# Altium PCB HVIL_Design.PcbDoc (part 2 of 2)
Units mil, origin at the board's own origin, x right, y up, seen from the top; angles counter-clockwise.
Board outline 4950 x 3450 mil, 2 copper layers (Top Layer, Bottom Layer), stack 62 mil thick; 93 components, 48 nets, 203 pads, 53 vias.
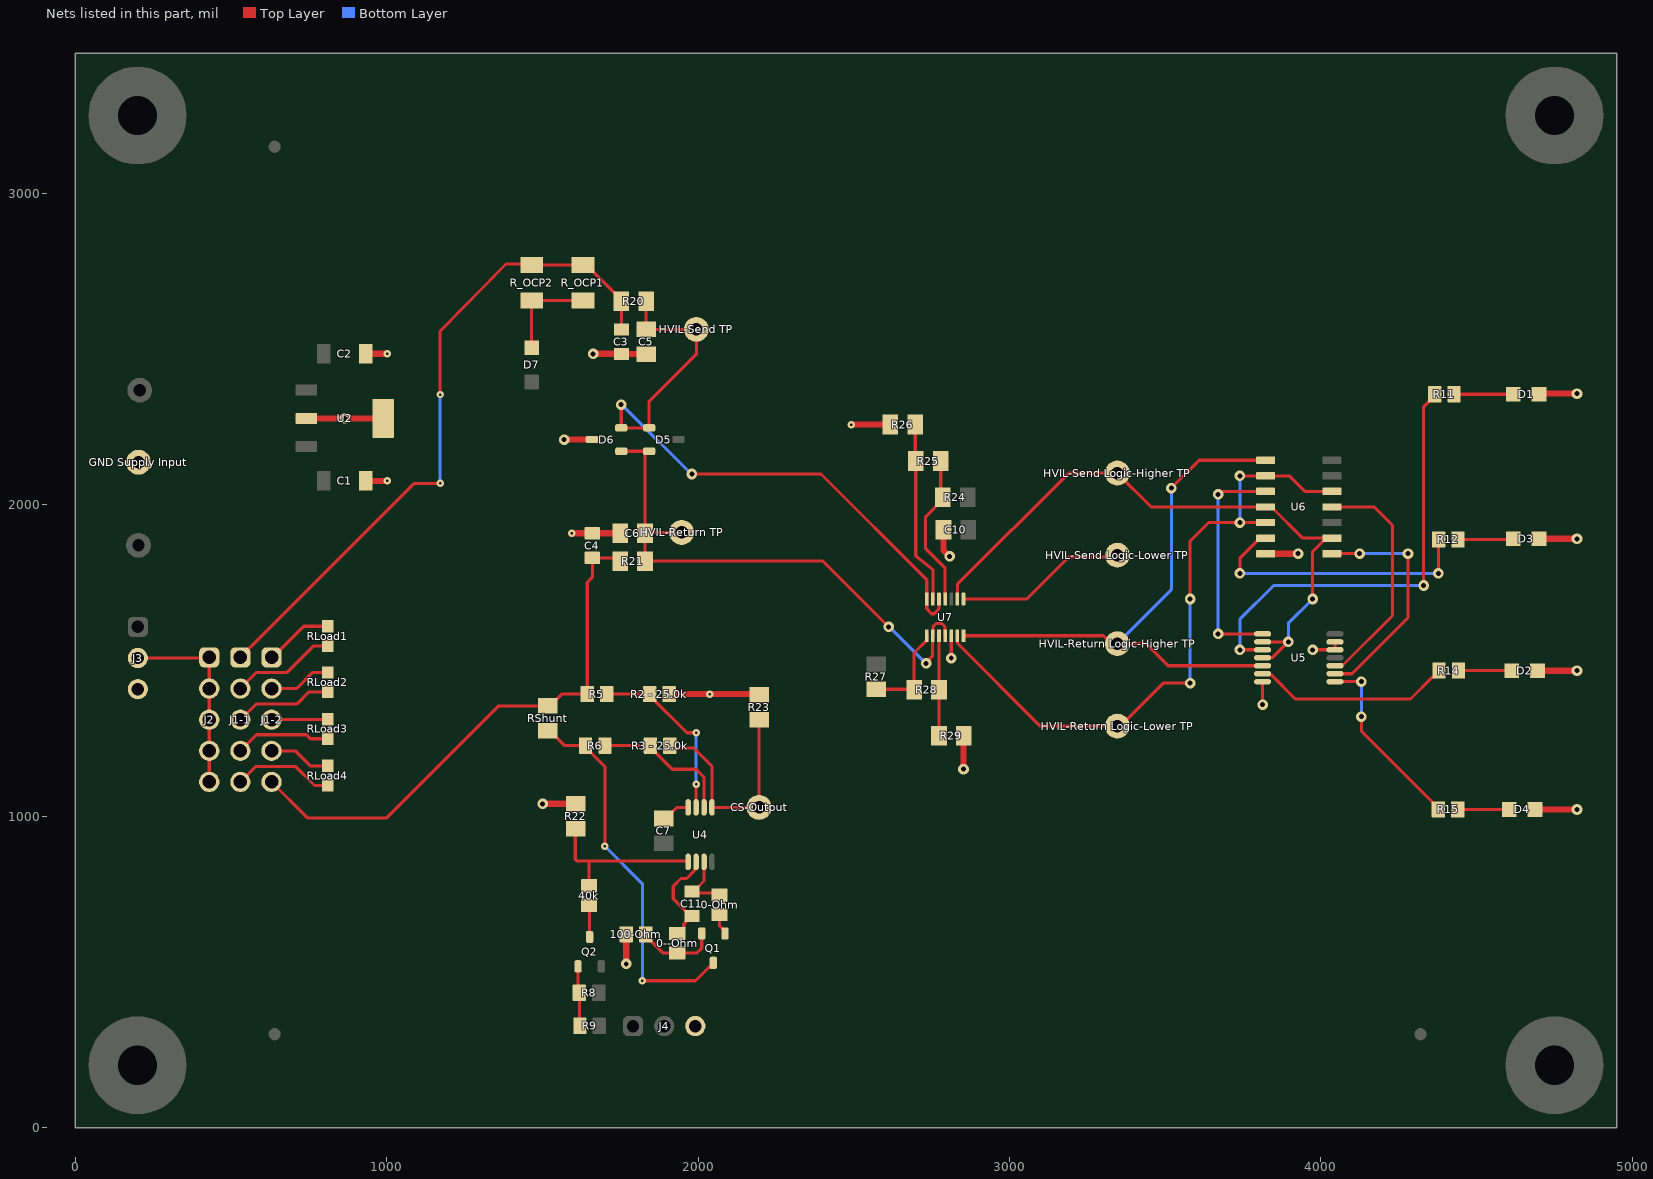
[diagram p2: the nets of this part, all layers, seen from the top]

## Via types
v1: diameter 34, hole 16, Top Layer to Bottom Layer, tented both sides, 42 vias
v2: diameter 24, hole 8, Top Layer to Bottom Layer, tented both sides, 11 vias

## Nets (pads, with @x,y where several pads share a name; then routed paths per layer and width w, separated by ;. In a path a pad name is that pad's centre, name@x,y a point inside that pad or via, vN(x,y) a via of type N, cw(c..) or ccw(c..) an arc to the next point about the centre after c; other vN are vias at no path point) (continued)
GND: 100-Ohm.2 "GND Supply Input.1" "R2 - 25.0k.2" C1.1 C2.1 C3.2 C4.2 C5.1 C6.1 C7.2 C10.2 D1.2 D2.2 D3.2 D4.2 D6.3 J3.3 J4.3 R22.2 R23.2 R26.2 R29.2 U2.2 U2.4 U4.4 U5.7 U5.12 U5.13 U6.7 U7.12 | length 2583.6
  Top Layer w10: C1.1@932.09,2076.77 C1.1@932.09,2086.61 ; C2.1@932.09,2475.21 C2.1@932.09,2485.06 ; v2(1594.88,1908.39) v2@1594.96,1908.46 ; C6.1@1749.3,1908.46 C6.1@1749.37,1908.39 ; C3.2@1753.13,2485.06 C3.2@1753.94,2484.25 ; 100-Ohm.2@1766.35,617.62 100-Ohm.2@1769.27,620.53 ; C5.1@1832.68,2484.25 C5.1@1833.31,2483.62 ; C7.2@1890,992.72 1896.5,992.72 1932.14,1028.36 U4.4@1967.84,1028.36 ; R23.2@2193.39,1392.13 R23.2@2195.87,1389.65 ; v1(2812.99,1507.78) U7.12@2812.99,1579.57 ; R29.2@2852.36,1257.65 R29.2@2853.62,1258.91 ; v1(3812.99,1358.41) U5.7@3812.99,1432.09 ; v1(3973.58,1534.45) U5.12@4045.28,1534.45 U5.13@4045.28,1560.04 ; D1.2@4700.79,2355.31 D1.2@4702.76,2357.28
  Top Layer w20: U2.2@742.13,2277.56 v1(865.16,2277.56) U2.4@988.19,2277.56 ; C1.1@932.09,2076.77 v2(1001.97,2076.77) ; C2.1@932.09,2485.06 v2(1001.97,2485.06) ; v1(1500.72,1039.72) R22.2@1607.29,1039.72 ; v1(1570.03,2209.66) D6.3@1658.82,2209.66 ; v2@1594.96,1908.46 C4.2@1660.43,1908.46 ; v1(1663.03,2485.06) C3.2@1753.13,2485.06 ; C4.2@1664.57,1908.46 C6.1@1749.3,1908.46 ; C3.2@1753.94,2484.25 C5.1@1832.68,2484.25 ; v1(1769.27,525.65) 100-Ohm.2@1769.27,620.53 ; 1907.23,1392.13 v2(2037.69,1392.13) R23.2@2193.39,1392.13 ; v2(2492.36,2257.87) R26.2@2617.48,2257.87 ; C10.2@2788.03,1920 2788.03,1853.84 v1(2807.62,1834.25) ; v1(2852.36,1150.99) R29.2@2852.36,1257.65 ; U6.7@3822.83,1843.11 v1(3927.17,1843.11) ; D4.2@4687.72,1021.65 v1(4822.56,1021.65) ; D2.2@4696.07,1467.52 v1(4822.56,1467.52) ; D3.2@4700.79,1891.05 v1(4822.56,1891.05) ; D1.2@4702.76,2357.28 v1(4822.56,2357.28)
"HVIL-Return Logic-Higher": "HVIL-Return Logic-Higher TP.1" U5.5 U6.1 U7.14 | length 1912
  Top Layer w10: U7.14@2852.36,1579.57 3302.08,1579.57 3327.51,1554.13 3346.46,1554.13 3439.14,1554.13 3510,1483.27 U5.5@3812.99,1483.27 ; v1(3520,2053.94) 3609.17,2143.11 U6.1@3822.83,2143.11
  Bottom Layer w10: 3346.46,1554.13 3520,1727.68 v1(3520,2053.94)
"HVIL-Return Logic-Lower": "HVIL-Return Logic-Lower TP.1" U6.2 U6.5 U6.12 U7.13 | length 2128.4
  Top Layer w10: U7.13@2832.68,1579.57 2833.58,1578.66 2833.58,1554.71 3098.92,1289.37 3346.46,1289.37 3355.61,1289.37 3493.51,1427.27 v1(3580,1427.27) ; v1(3580,1697.68) 3580,1883.11 3640,1943.11 v1(3740,1943.11) U6.5@3822.83,1943.11 ; v1(3740,2093.11) U6.2@3822.83,2093.11 3898.82,2093.11 3948.82,2043.11 U6.12@4035.43,2043.11
  Bottom Layer w10: v1(3580,1427.27) v1(3580,1697.68) ; v1(3740,1943.11) v1(3740,2093.11)
"HVIL-Send Logic-Higher": "HVIL-Send Logic-Higher TP.1" U5.2 U5.4 U6.4 U6.9 U7.2 | length 2053.8
  Top Layer w10: U7.2@2832.68,1697.68 2832.68,1744.65 3190,2101.97 3346.46,2101.97 3455.32,1993.11 U6.4@3822.83,1993.11 3841.54,1993.11 3941.54,1893.11 U6.9@4016.73,1893.11 ; U5.4@3812.99,1508.86 3814.47,1510.34 3845.82,1510.34 v1(3895.53,1560.04) U5.2@3812.99,1560.04 ; v1(3973.58,1697.68) 3973.58,1849.96 U6.9@4016.73,1893.11 ; U6.9@4035.43,1893.11 U6.9@4016.73,1893.11
  Bottom Layer w10: v1(3895.53,1560.04) 3895.53,1619.63 v1(3973.58,1697.68)
"HVIL-Send Logic-Lower": "HVIL-Send Logic-Lower TP.1" U7.1 | length 552.4
  Top Layer w10: U7.1@2852.36,1697.68 3055.4,1697.68 3190,1832.28 3340.34,1832.28 3346.46,1838.4
Net0--Ohm_1: 0--Ohm.1 100-Ohm.1 Q1.2 | length 261
  Top Layer w10: 100-Ohm.1@1831.77,620.53 1831.77,615.78 1886.54,561.01 0--Ohm.1@1932.95,561.01 1996.5,561.01 2011.77,576.28 Q1.2@2011.77,623.51
Net0--Ohm_2: 0--Ohm.2 C11.2 U4.6 | length 318.5
  Top Layer w10: 0--Ohm.2@1932.95,623.51 1937.7,623.51 1953.95,639.76 1953.95,653.18 1960.67,659.91 1960.67,664.83 C11.2@1975.36,679.51 ; C11.2@1980.28,679.51 C11.2@1975.36,679.51 ; U4.6@1993.43,853.16 1993.43,833.36 1989.57,829.5 1989.57,826.44 1963.13,800 1945.2,800 1920.32,775.12 1920.32,734.55 C11.2@1975.36,679.51
Net0-Ohm_1: 0-Ohm.1 Q1.1 | length 68.3
  Top Layer w10: 0-Ohm.1@2068.86,684 2068.86,647.75 2078.98,637.64 2079.84,637.64 2086.58,630.9 Q1.1@2086.58,623.51
Net0-Ohm_2: 0-Ohm.2 C11.1 U4.7 | length 207.3
  Top Layer w10: U4.7@2019.02,853.16 2019.02,792.08 1985.2,758.25 C11.1@1980.28,758.25 1985.34,753.19 2062.18,753.19 0-Ohm.2@2068.86,746.5
Net40k_1: 40k.1 Q2.3 | length 102.4
  Top Layer w10: 40k.1@1649.83,714 1651.57,712.27 Q2.3@1651.57,612.33
Net40k_2: 40k.2 R22.1 U4.5 | length 544.7
  Top Layer w10: R22.1@1607.29,959.72 1605.56,957.98 1605.56,861.74 1610.66,856.64 1649.83,856.64 ; 40k.2@1649.83,776.5 1649.83,856.64 ; U4.5@1967.84,853.16 1964.36,856.64 1649.83,856.64
NetC5_2: "HVIL-Send TP.1" C5.2 D5.1 D6.2 R20.2 U7.5 U7.7 | length 2186.3
  Top Layer w10: v1(1753.13,2321.62) 1753.22,2321.53 1753.22,2247.15 D6.2@1753.31,2247.06 D5.1@1842.91,2247.06 1842.91,2332.42 1994.43,2483.94 1994.43,2563.62 C5.2@1833.31,2563.62 R20.2@1833.31,2653.54 ; v1(1980,2099.18) 2394.55,2099.18 2734.25,1759.48 U7.7@2734.25,1697.68 2734.25,1665.75 2749.72,1650.28 2758,1650.28 2773.62,1665.91 U7.5@2773.62,1697.68
  Bottom Layer w10: v1(1753.13,2321.62) 1755.35,2321.62 1977.79,2099.18 v1(1980,2099.18)
NetC6_2: "HVIL-Return TP.1" C6.2 D5.2 D6.1 R21.2 U7.9 U7.11 | length 1819.5
  Top Layer w10: D6.1@1753.31,2172.26 D5.2@1836.11,2172.26 ; D5.2@1842.91,2172.26 D5.2@1836.11,2172.26 ; 1947.12,1911.42 1832.4,1911.42 C6.2@1829.37,1908.39 ; v1@2611.65,1601.77 v1(2611.65,1608.27) 2400.49,1819.43 R21.2@1829.37,1819.43 C6.2@1829.37,1908.39 ; v1(2732.5,1491.09) 2732.5,1494.7 2753.32,1515.52 2753.32,1578.95 U7.9@2753.94,1579.57 2753.94,1608.27 2764.76,1619.09 2782.13,1619.09 2793.31,1607.91 U7.11@2793.31,1572.83 ; C6.2@1829.37,1908.39 1829.37,2165.52 D5.2@1836.11,2172.26
  Bottom Layer w10: v1(2611.65,1608.27) 2613.49,1608.27 2730.67,1491.09 v1(2732.5,1491.09)
NetCS-Output_1: "R3 - 25.0k.2" CS-Output.1 R23.1 U4.1 | length 727.7
  Top Layer w10: 1909.2,1226.55 1916.84,1218.91 1986.54,1218.91 2044.61,1160.84 U4.1@2044.61,1028.36 CS-Output.1@2195.87,1028.36 R23.1@2195.87,1309.65
NetD1_1: D1.1 R11.2 | length 190.1
  Top Layer w10: R11.2@4428.04,2355.31 D1.1@4618.11,2355.31
NetD2_1: D2.1 R14.2 | length 171.7
  Top Layer w10: R14.2@4441.68,1467.52 D2.1@4613.39,1467.52
NetD3_1: D3.1 R12.2 | length 178.1
  Top Layer w10: R12.2@4440.81,1889.09 4616.14,1889.09 D3.1@4618.11,1891.05
NetD4_1: D4.1 R15.2 | length 165.3
  Top Layer w10: R15.2@4439.79,1021.65 D4.1@4605.05,1021.65
NetD7_1: D7.1 R_OCP1.1 R_OCP2.1 | length 316.5
  Top Layer w10: D7.1@1465.55,2504.74 R_OCP2.1@1465.55,2656.5 R_OCP1.1@1630.31,2656.5
NetQ1_3: Q1.3 R6.1 RShunt.2 | length 1227.4
  Top Layer w10: RShunt.2@1517.72,1274.37 1524.22,1274.37 1572.04,1226.55 R6.1@1638.45,1226.55 1638.45,1221.8 1700.95,1159.3 v2(1700.95,903.36) ; v2(1821.1,471.59) 1991.74,471.59 2035.05,514.9 2042.43,514.9 2049.18,521.64 Q1.3@2049.18,529.02
  Bottom Layer w10: v2(1700.95,903.36) 1821.1,783.21 v2(1821.1,471.59)
NetQ2_1: Q2.1 R8.2 R9.2 | length 193.3
  Top Layer w10: Q2.1@1614.17,517.84 1614.17,437.61 R8.2@1618.58,433.2 1619.45,432.33 1619.45,328 R9.2@1620.32,327.13
"NetR2 - 25.0k_1": "R2 - 25.0k.1" R5.2 U4.3 | length 580.8
  Top Layer w10: R5.2@1706.45,1392.13 1844.73,1392.13 1844.73,1387.38 1964.22,1267.89 v2(1993.43,1267.89) ; U4.3@1993.43,1028.36 v2(1993.43,1103.22)
  Bottom Layer w10: v2(1993.43,1103.22) v2(1993.43,1267.89)
"NetR3 - 25.0k_1": "R3 - 25.0k.1" R6.2 U4.2 | length 459.8
  Top Layer w10: R6.2@1700.95,1226.55 1846.7,1226.55 1846.7,1221.8 1917.52,1150.99 1993.43,1150.99 2019.02,1125.39 U4.2@2019.02,1028.36
NetR11_1: R11.1 U5.3 | length 1435.7
  Top Layer w10: v1(3740,1534.45) U5.3@3812.99,1534.45 ; v1(4330,1740.99) 4330,2315.03 4365.54,2350.56 R11.1@4365.54,2355.31
  Bottom Layer w10: v1(3740,1534.45) 3740,1632.17 3848.82,1740.99 4299.36,1740.99 ; 4300,1740.34 4299.36,1740.99 ; v1(4330,1740.99) 4299.36,1740.99
NetR12_1: R12.1 U6.6 | length 905.2
  Top Layer w10: v1(3740,1780) 3740,1828.98 3804.13,1893.11 U6.6@3822.83,1893.11 ; v1(4377.29,1780) 4377.29,1888.06 R12.1@4378.31,1889.09
  Bottom Layer w10: v1(3740,1780) v1(4377.29,1780)
NetR14_1: R14.1 U5.6 | length 640.5
  Top Layer w10: U5.6@3812.99,1457.68 3833.78,1457.68 3837.64,1453.82 3840.69,1453.82 3918.31,1376.21 4287.87,1376.21 4358.18,1446.52 4362.93,1446.52 4379.18,1462.77 R14.1@4379.18,1467.52
NetR15_1: R15.1 U5.8 | length 597.6
  Top Layer w10: U5.8@4045.28,1432.09 v1(4130,1432.09) ; v1(4130,1320) 4130,1273.69 4377.29,1026.4 R15.1@4377.29,1021.65
  Bottom Layer w10: v1(4130,1320) v1(4130,1432.09)
NetR24_2: R24.2 R25.1 U7.4 | length 495
  Top Layer w10: R25.1@2779.17,2140.76 2779.17,2031.35 R24.2@2786.32,2024.2 2786.32,2017.7 2730.67,1962.04 2730.67,1859.43 2793.31,1796.79 U7.4@2793.31,1697.68
NetR25_2: R25.2 R26.1 U7.6 | length 593.7
  Top Layer w10: R26.1@2697.48,2257.87 2697.48,2142.46 R25.2@2699.17,2140.76 2699.17,1835.53 2702.13,1832.58 2753.94,1790.89 U7.6@2753.94,1690.94
NetR27_2: R27.2 R28.1 U7.8 | length 312.9
  Top Layer w10: R27.2@2571.65,1407.78 2691.99,1407.78 R28.1@2693.62,1406.14 2693.62,1524.18 2734.25,1564.81 U7.8@2734.25,1579.57
NetR28_2: R28.2 R29.1 U7.10 | length 320.7
  Top Layer w10: R29.1@2773.62,1258.91 R28.2@2773.62,1406.14 U7.10@2773.62,1579.57
NetU5_1: U5.1 U6.3 | length 747.7
  Top Layer w10: v1(3670,1585.63) U5.1@3812.99,1585.63 ; v1(3670,2033.5) 3676.49,2033.5 3686.11,2043.11 U6.3@3822.83,2043.11
  Bottom Layer w10: v1(3670,1585.63) v1(3670,2033.5)
NetU5_9: U5.9 U6.8 | length 759.3
  Top Layer w10: U6.8@4035.43,1843.11 v1(4124.63,1843.11) ; U5.9@4045.28,1457.68 4100,1457.68 4280,1637.68 v1(4280,1843.11)
  Bottom Layer w10: v1(4124.63,1843.11) v1(4280,1843.11)
NetU5_10: U5.10 U6.11 | length 760.4
  Top Layer w10: U6.11@4035.43,1993.11 4171.14,1993.11 4230,1934.25 4230,1644.15 4072.98,1487.13 4069.92,1487.13 4066.06,1483.27 U5.10@4045.28,1483.27
Pin1: C3.1 J1-1.1 R20.1 R_OCP1.2 R_OCP2.2 | length 2174.3
  Top Layer w10: J1-1.1@530,1510 1088.9,2068.9 v2(1171.26,2068.9) ; v2(1171.26,2354.33) 1171.26,2557.09 1382.87,2773.62 R_OCP2.2@1462.6,2773.62 ; R_OCP2.2@1465.55,2770.67 R_OCP1.2@1630.31,2770.67 1641.14,2770.67 1731.77,2680.04 1733.31,2680.04 1753.31,2660.04 R20.1@1753.31,2653.54 1753.94,2652.91 C3.1@1753.94,2562.99
  Bottom Layer w10: v2(1171.26,2068.9) v2(1171.26,2354.33)
Pin2: J1-2.1 RLoad1.1 | length 221.6
  Top Layer w10: J1-2.1@630,1510 633.43,1510 733.66,1610.24 RLoad1.1@810.04,1610.24
Pin3: J1-1.2 RLoad1.2 | length 336.9
  Top Layer w10: J1-1.2@530,1410 581.81,1461.81 680,1461.81 765.43,1547.24 RLoad1.2@810.04,1547.24
Pin4: J1-2.2 RLoad2.1 | length 216.4
  Top Layer w10: J1-2.2@640.52,1420.52 J1-2.2@630,1410 710.53,1410 762.34,1461.81 RLoad2.1@810.04,1461.81
Pin5: J1-1.3 RLoad2.2 | length 328.5
  Top Layer w10: J1-1.3@530,1310 580,1360 710.53,1360 749.35,1398.82 RLoad2.2@810.04,1398.82
  Bottom Layer w10: J1-1.3@543.31,1311.81 J1-1.3@551.58,1320.09
Pin6: J1-2.3 RLoad3.1 | length 180.8
  Top Layer w10: J1-2.3@630,1310 808.23,1310 RLoad3.1@810.04,1311.81
Pin7: J1-1.4 RLoad3.2 | length 306.7
  Top Layer w10: J1-1.4@530,1210 581.61,1261.61 742.13,1261.61 754.92,1248.82 RLoad3.2@810.04,1248.82
Pin8: J1-2.4 RLoad4.1 | length 201
  Top Layer w10: J1-2.4@630,1210 706.73,1210 754.92,1161.81 RLoad4.1@810.04,1161.81 RLoad4.1@810.04,1162.8
Pin9: J1-1.5 RLoad4.2 | length 326.1
  Top Layer w10: J1-1.5@530,1110 580,1160 706.73,1160 767.91,1098.82 RLoad4.2@810.04,1098.82
Pin10: C4.1 J1-2.5 R5.1 R21.1 RShunt.1 | length 1763.9
  Top Layer w10: J1-2.5@630,1110 745.28,994.72 1000,994.72 1359.65,1354.37 RShunt.1@1517.72,1354.37 1524.22,1354.37 1561.97,1392.13 R5.1@1643.95,1392.13 1643.95,1750.59 1660.43,1767.07 C4.1@1660.43,1829.72 1739.08,1829.72 R21.1@1749.37,1819.43
VBus: J2.1 J2.2 J2.3 J2.4 J2.5 J3.2 | length 630
  Top Layer w10: J3.2@200.79,1508.06 428.06,1508.06 J2.1@430,1510 J2.2@430,1410 J2.3@430,1310 J2.4@430,1210 J2.5@430,1110
pads on no net: FID1.1 FID2.1 FID3.1 H1.1 H2.1 H3.1 H4.1 H5.0 H6.0 H7.0 H8.0 H9.0 H10.0 H11.0 H12.0 LBL1.0 U5.11

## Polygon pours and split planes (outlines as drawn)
GND on Bottom Layer "BOTTOM_LAYER_GND_P000" (solid, remove dead copper, pour order 0): 0,0 4950,0 4950,3450 0,3450
GND on Top Layer "TOP_LAYER_GND_P001" (solid, remove dead copper, pour order 1): 0,0 4950,0 4950,3450 0,3450

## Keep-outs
Keep-Out Layer:
  text ".Layer_Name" at 577,-858.49 h60

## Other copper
Top Layer:
  text ".Layer_Name" at 577,-858.49 h60
Bottom Layer:
  text ".Layer_Name" at 577,-858.49 h60

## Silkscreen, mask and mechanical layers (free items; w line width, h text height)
Top Overlay:
  text "Normal Operation" at 4434.04,2426 h30
  text "Open Connection" at 4445.16,1969.93 h30
  text "Short to Battery" at 4445.16,1544.54 h30
  text "Short to Ground" at 4473.71,1086 h30
  text "'.PRJ_Number'.PCB_Rev" at 1845,125.77 h108.27
  text ".Layer_Name" at 577,-858.49 h60
Bottom Overlay:
  text ".Layer_Name" at 577,-858.49 h60
Top Paste:
  text ".Layer_Name" at 577,-858.49 h60
Bottom Paste:
  text ".Layer_Name" at 577,-858.49 h60
Top Solder:
  text ".Layer_Name" at 577,-858.49 h60
  text ".Layer_Name" at 577,-858.49 h60
Bottom Solder:
  text ".Layer_Name" at 577,-858.49 h60
Drill Guide:
  text ".Layer_Name" at 577,-858.49 h60
M1 Board Outline:
  the board outline again, w10
  text ".Layer_Name" at 577,-858.49 h60
M2 Board Dimensions:
  rectangle: 125,-400 500,-275
  rectangle: 0,-275 125,-150
  lines w7: 0,-275 1000,-275 ; 125,-400 125,-150 ; 250,-400 250,-150 ; 500,-400 500,-150 ; 750,-400 750,-150 ; 0,-400 0,-150 1000,-150 1000,-400 0,-400
  text ".Layer_Name" at 577,-858.49 h60
M3 3D STEP Top:
  text ".Layer_Name" at 577,-858.49 h60
M4 3D STEP Bottom:
  text ".Layer_Name" at 577,-858.49 h60
M5 Assembly Top:
  lines w10: -292,-930.17 6308,-930.17 ; -292,-726.83 6310,-726.83 ; -292,-523.5 -292,-1133.5 3713,-1133.5 6310,-1133.5 6310,-523.5 -291.5,-523.5 -291.5,-1133.5 1284,-1133.5 ; 2173,-1133.5 2173,-523.5 ; 3440,-726.83 3440,-523.5 ; 4280,-726.83 4280,-523.5 ; 4902,-1140 4902,-937.17
  text "COMPONENTS MARKED 'DNP' SHOULD NOT BE POPULATED." at 1153.5,-318.5 h60
  text "ASSEMBLY VARIANT:" at 1153,-434 h60
  text ".VariantName" at 2189,-434 h60
  text "PCB VIEWED FROM TOP SIDE" at -228.5,-655.67 h60
  text "BOARD #:" at 2248,-655.67 h60
  text ".PRJ_Number" at 2793.5,-655.67 h60
  text "REV:" at 3638,-655.67 h60
  text ".PCB_Rev" at 3929.5,-655.67 h60
  text "SVN REV:" at 4476,-655.67 h60
  text ".VersionControl_RevNumber" at 4982,-655.67 h60
  text "PLOT NAME =" at -228.5,-1064.34 h60
  text ".plot_File_Name" at 577,-1064.34 h60
  text "GENERATED    :" at 2250,-1064.34 h60
  text ".Print_Date" at 3119.5,-1064.34 h60
  text ".Print_Time" at 3848.5,-1064.34 h60
  text "TEXAS INSTRUMENTS" at 5113,-1064.34 h60
M6 Assembly Bottom:
  lines w10: -292.5,-727.33 6309.5,-727.33 ; -290.5,-930.67 6309.5,-930.67 ; 1115.5,-1140.5 1115.5,-937.67 ; 1737.5,-727.33 1737.5,-524 ; 2577.5,-727.33 2577.5,-524 ; 3844.5,-1134 3844.5,-524 ; 4733.5,-1134 6309,-1134 6309,-524 -292.5,-524 -292.5,-1134 2304.5,-1134 6309.5,-1134 6309.5,-524
  text "COMPONENTS MARKED 'DNP' SHOULD NOT BE POPULATED." at 6102,-318 h60
  text ".VariantName" at 5058,-434 h60
  text "ASSEMBLY VARIANT:" at 6097,-434 h60
  text ".VersionControl_RevNumber" at 1035.5,-656.17 h60
  text "SVN REV:" at 1541.5,-656.17 h60
  text ".PCB_Rev" at 2088,-656.17 h60
  text "REV:" at 2379.5,-656.17 h60
  text ".PRJ_Number" at 3224,-656.17 h60
  text "BOARD #:" at 3769.5,-656.17 h60
  text "PCB VIEWED FROM BOTTOM SIDE" at 6246,-656.17 h60
  text "TEXAS INSTRUMENTS" at 904.5,-1064.84 h60
  text ".Print_Time" at 2169,-1064.84 h60
  text ".Print_Date" at 2898,-1064.84 h60
  text "GENERATED    :" at 3767.5,-1064.84 h60
  text ".plot_File_Name" at 5440.5,-1064.84 h60
  text "PLOT NAME =" at 6246,-1064.84 h60
M9 Title Sheet:
  drawing of 56 lines, arcs and shapes, not listed
  text "1" at 1058.34,13381.39 h70
  text "2" at 4384,13381.39 h70
  text "3" at 7714,13381.39 h70
  text "4" at 11049,13381.39 h70
  text "5" at 14374,13381.39 h70
  text "6" at 17709,13381.39 h70
  text "A" at -463,11603.39 h70
  text "A" at 19237,11603.39 h70
  text "B" at -463,7853.39 h70
  text "B" at 19237,7853.39 h70
  text "C" at -463,4103.39 h70
  text "C" at 19237,4103.39 h70
  text "D" at -463,353.39 h70
  text "D" at 19237,353.39 h70
  text "PROJECT TITLE:" at 16143,268.39 h45
  text ".PRJ_Title" at 16193,135.06 h70
  text "DESIGNED FOR:" at 16143,-32.61 h45
  text ".PRJ_Customer" at 16193,-172.61 h70
  text "FILE NAME:" at 16143,-332.61 h45
  text ".PCB_File_Name_No_Path" at 16193,-452.61 h70
  text "Texas Instruments (TI) and/or its licensors do not warrant the accuracy or completeness of this specification" at 11173.5,-614.45 h45
  text "ENGINEER:" at 16143,-622.61 h45
  text "LAYOUT BY:" at 17648,-622.61 h45
  text "or any information contained therein. TI and/or its licensors do not warrant that this design will meet" at 11128.51,-727.11 h45
  text ".PRJ_Engineer" at 16193,-777.6 h70
  text ".PCB_Layout" at 17698.5,-777.6 h70
  text "the specifications, will be suitable for your application or fit for any particular purpose, or will operate in" at 11128.51,-839.78 h45
  text ".Layer_Name" at 577,-858.49 h60
  text "ALTIUM DESIGNER VERSION:" at 17648,-932.61 h45
  text "an implementation. TI and/or its licensors do not warrant that the design is production worthy. You should" at 11128.51,-952.44 h45
  text "completely validate and test your design implementation to confirm the system functionality for your application." at 11173.5,-1065.11 h45
  text ".print_Scale" at 16193,-1065.94 h70
  text ".Application_BuildNumber" at 17698.5,-1065.94 h70
  text "1" at 1058.34,-1318.61 h70
  text "2" at 4384,-1318.61 h70
  text "3" at 7714,-1318.61 h70
  text "4" at 11049,-1318.61 h70
  text "5" at 14374,-1318.61 h70
  text "6" at 17709,-1318.61 h70
M10 Fab Notes:
  drawing of 189 lines, arcs and shapes, not listed
  text "DESIGN INFORMATION" at 17178.02,6365.17 h60
  text "MIN. TRACK WIDTH:" at 16533.46,6233.05 h60
  text "8" at 17629.7,6233.05 h60
  text "MIL" at 17784.46,6233.05 h60
  text "MIN. CLEARANCE:" at 16533.46,6108.92 h60
  text "MIL" at 17784.46,6108.92 h60
  text "7.874" at 17459.65,6104.33 h60
  text "MIN. VIA PAD SIZE:" at 16533.46,5984.8 h60
  text "24" at 17599.71,5984.8 h60
  text "MIL" at 17784.46,5984.8 h60
  text "0.05mm (2MIL)" at 17228.46,5854.9 h60
  text "MINIMUM ANNULAR RING" at 16204.23,5846.67 h60
  text "EXTERNAL" at 17936.46,5846.67 h60
  text "PER" at 16404.23,5736.55 h60
  text "IPC-D-275 CLASS 2 LEVEL C" at 16624.23,5736.54 h60
  text "MIL, HOLES" at 18112.46,5636.07 h60
  text "+/-" at 17720,5627.48 h60
  text "+/-" at 18574,5627.48 h60
  text "REGISTRATION TOLERANCES:" at 16204.23,5626.42 h60
  text "METAL" at 17404,5626.42 h60
  text "5" at 17980.2,5626.42 h60
  text "3" at 18813.2,5626.42 h60
  text "MIL" at 18929.46,5626.42 h60
  text "HOLE SIZE TOLERANCE (UNLESS OTHERWISE SPECIFIED):" at 16204.23,5528.1 h60
  text "+/-" at 18574,5525.23 h60
  text "3" at 18813.2,5524.17 h60
  text "MIL" at 18929.46,5524.17 h60
  text "MATERIAL:" at 16129.46,5386.52 h60
  text "FR-4 High Tg" at 17115.9,5258 h60
  text "X" at 16971.46,5250.01 h60
  text "FR-4" at 16550.46,5245.49 h60
  text "OTHER" at 18038.46,5245.49 h60
  text "62 MIL (1.6mm) +/-10%" at 16870.56,5102.46 h60
  text "X" at 16750.46,5100.01 h60
  text "THICKNESS:" at 16204.23,5094.24 h60
  text "OTHER" at 18155.46,5094.24 h60
  text "TOLERANCE:" at 16204.23,4955.92 h60
  text "X" at 17052.46,4955.92 h60
  text "ANSI IPC-6012 TYPE 3 CLASS 2" at 17230.48,4955.92 h60
  text "OTHER +/-" at 17230.46,4811.73 h60
  text "BOW & TWIST:" at 16204.23,4666.54 h60
  text "X" at 17052.46,4666.54 h60
  text "ANSI IPC-6012 TYPE 3 CLASS 2" at 17230.48,4666.54 h60
  text "OTHER +/-" at 17230.46,4519.85 h60
  text "DRILLING:" at 16129.46,4389.23 h60
  text "NC_DRILL FILES" at 17890.46,4284.04 h60
  text "REFERENCE:" at 16204.23,4280.1 h60
  text "X" at 16861.46,4280.01 h60
  text "AS SHOWN" at 17039.46,4280.1 h60
  text "X" at 17762.46,4280.1 h60
  text "OTHER" at 18188.46,4137.85 h60
  text "PTH COPPER THICKNESS:" at 16203.91,4134.32 h60
  text "X" at 17343.14,4134.32 h60
  text "20-30 um" at 17471.14,4134.32 h60
  text "BOARD FINISH:" at 16129.46,3986.73 h60
  text "SILKSCREEN:" at 16284.68,3876.6 h60
  text "X" at 17242.46,3876.6 h60
  text "TOP" at 17359.46,3876.6 h60
  text "X" at 17752.46,3876.6 h60
  text "BOTTOM" at 17870.46,3876.6 h60
  text "SILKSCREEN COLOR:" at 16284.68,3721.41 h60
  text "X" at 17241.46,3721.41 h60
  text "WHITE" at 17359.46,3721.41 h60
  text "OTHER" at 17870.46,3721.41 h60
  text "X" at 17372.46,3577.96 h60
  text "GREEN" at 17490.46,3577.96 h60
  text "OTHER" at 18108.46,3577.96 h60
  text "SOLDER RESIST COLOR:" at 16284.68,3571.1 h60
  text "X" at 17372.46,3423.71 h60
  text "MATTE" at 17490.46,3423.71 h60
  text "SEMI-GLOSS" at 18108,3423.07 h60
  text "IMMERSION GOLD (ENIG)" at 17190.46,3250.94 h60
  text "ENEPIG" at 18528,3243.72 h60
  text "SURFACE FINISH:" at 16129.46,3242.72 h60
  text "X" at 17012.46,3242.72 h60
  text "IMM. TIN/SILVER OR EQUIV" at 16459,3105.4 h60
  text "OTHER" at 17890.46,3101.47 h60
  text "ARRAY/PANEL:" at 16129.46,2946.09 h60
  text "CUT AND TRIM PER M1 BOARD OUTLINE" at 17190.46,2937.87 h60
  text "N.C. ROUTE" at 17190.46,2801.9 h60
  text "X" at 17878.46,2801.9 h60
  text "V. SCORE" at 18056.46,2801.9 h60
  text "CERTIFICATION:" at 16129.46,2672.77 h60
  text "MATERIALS AND WORKMANSHIP FOR ALL PCBS" at 16854.46,2672.77 h60
  text "TO MEET OR EXCEED THE REQUIREMENTS OF:" at 16854.46,2578.71 h60
  text "X" at 16491.97,2450.08 h60
  text "ANSI IPC-A-600F CLASS ->" at 16619.96,2450.08 h60
  text "X" at 18267.97,2450.08 h60
  text "2" at 18377.96,2450.08 h60
  text "1" at 18062.96,2448.58 h60
  text "3" at 18731.96,2448.58 h60
  text "X" at 17303.97,2302.39 h60
  text "RoHS" at 17431.96,2302.39 h60
  text "OTHER" at 18076.36,2302.39 h60
  text "PER ORDER" at 18473.42,2302.39 h60
  text "ALL BOARDS MUST MEET OR EXCEED UL94-V0 REQUIREMENTS." at 16157,2148.57 h60
  text "PCB MUST BEAR THE UL94V-0 UL REGISTERED MATERIAL ID NUMBER" at 16157,2032.5 h60
  text "ADDITIONAL REQUIREMENTS:" at 16129.46,1863.08 h60
  text "MICROSECTION:" at 16204.23,1755.95 h60
  text "YES" at 17109.96,1755.95 h60
  text "REQUIRED" at 17971.46,1611.62 h60
  text "BARE BOARD ELEC. TEST:" at 16204.23,1608.76 h60
  text "NONE" at 17509.96,1608.76 h60
  text "X" at 17853.46,1608.76 h60
  text "PER ORDER" at 18563.46,1608.76 h60
  text "XX MIL VIAS REQUIRE NON-CONDUCTIVE FILL AND PLANARIZE" at 16372.38,1403.82 h59
  text "XX MIL VIAS REQUIRE CONDUCTIVE FILL AND PLANARIZE" at 16380.38,1299.84 h60
  text "OUTER XX MIL TRACES REQUIRE 50 OHM SINGLE-ENDED IMPEDANCE" at 16379.39,1136.46 h58
  text "LAYER 2 & 3 (INNER LAYERS) XX MIL WIDE, XX MIL SPACE / TRACES REQUIRE 100 OHM DIFFERENTIAL IMPEDANCE" at 16371.39,900.74 h60
  text ".Layer_Name" at 577,-858.49 h60
M11 Gerber Information:
  lines w10: -292,-930.17 6308,-930.17 ; -292,-726.83 6310,-726.83 ; -292,-523.5 -292,-1133.5 3713,-1133.5 6310,-1133.5 6310,-523.5 -291.5,-523.5 -291.5,-1133.5 1284,-1133.5 ; 2173,-1133.5 2173,-523.5 ; 3440,-726.83 3440,-523.5 ; 4280,-726.83 4280,-523.5 ; 4902,-1140 4902,-937.17
  text "ALL ARTWORK VIEWED FROM TOP SIDE" at -228.5,-655.67 h60
  text "BOARD #:" at 2248,-655.67 h60
  text ".PRJ_Number" at 2793.5,-655.67 h60
  text "REV:" at 3638,-655.67 h60
  text ".PCB_Rev" at 3929.5,-655.67 h60
  text "SVN REV:" at 4476,-655.67 h60
  text ".VersionControl_RevNumber" at 4982,-655.67 h60
  text "LAYER NAME =" at -228.5,-858.49 h60
  text "PLOT NAME =" at -228.5,-1064.34 h60
  text ".plot_File_Name" at 577,-1064.34 h60
  text "GENERATED    :" at 2250,-1064.34 h60
  text ".Print_Date" at 3119.5,-1064.34 h60
  text ".Print_Time" at 3848.5,-1064.34 h60
  text "TEXAS INSTRUMENTS" at 5113,-1064.34 h60
M12 Stackup:
  drawing of 191 lines, arcs and shapes, not listed
  text "Layer" at 14605.06,13091.48 h60
  text "Name" at 15014.97,13091.48 h60
  text "Material" at 15944.72,13091.48 h60
  text "Thickness" at 16804.48,13091.48 h60
  text "Constant" at 17454.32,13091.48 h60
  text "Board Layer Stack" at 18024.18,13091.48 h60
  text "Top Overlay" at 15014.97,12971.48 h60
  text "Top Solder" at 15014.97,12851.48 h60
  text "Solder Resist" at 15944.72,12851.48 h60
  text "0.40mil" at 16804.48,12851.48 h60
  text "3.5" at 17454.32,12851.48 h60
  text "1" at 14605.06,12731.48 h60
  text "Top Layer" at 15014.97,12731.48 h60
  text "1.40mil" at 16804.48,12731.48 h60
  text "Dielectric1" at 15014.97,12611.48 h60
  text "FR-4 High Tg" at 15944.72,12611.48 h60
  text "59.20mil" at 16804.48,12611.48 h60
  text "4.8" at 17454.32,12611.48 h60
  text "2" at 14605.06,12491.48 h60
  text "Bottom Layer" at 15014.97,12491.48 h60
  text "1.40mil" at 16804.48,12491.48 h60
  text "Bottom Solder" at 15014.97,12371.48 h60
  text "Solder Resist" at 15944.72,12371.48 h60
  text "0.40mil" at 16804.48,12371.48 h60
  text "3.5" at 17454.32,12371.48 h60
  text "Bottom Overlay" at 15014.97,12251.48 h60
  text ".Layer_Name" at 577,-858.49 h60
M13 Component Bodies Top:
  text ".Layer_Name" at 577,-858.49 h60
M14 Component Bodies Bottom:
  text ".Layer_Name" at 577,-858.49 h60
M15 Courtyards Top:
  text ".Layer_Name" at 577,-858.49 h60
M16 Courtyards Bottom:
  text ".Layer_Name" at 577,-858.49 h60
Drill Drawing:
  circle w10: c5443.72,2787 r27.63
  lines w10: 5416.09,2897.51 5429.9,2897.51 5443.72,2883.7 5457.53,2897.51 5471.34,2897.51 5457.53,2911.32 5471.34,2925.14 5457.53,2925.14 5443.72,2938.95 5429.9,2925.14 5416.09,2925.14 5429.9,2911.32 5416.09,2897.51 ; 5416.09,3063.27 5471.34,3063.27 5443.72,3008.02 5416.09,3063.27 ; 5416.09,3132.34 5471.34,3132.34 5471.34,3187.59 5416.09,3187.59 5416.09,3132.34 ; 5416.09,3256.66 5443.72,3270.47 5471.34,3256.66 5457.53,3284.28 5471.34,3311.91 5443.72,3298.1 5416.09,3311.91 5429.9,3284.28 5416.09,3256.66
  lines w12: 5366,2722.08 8597.49,2722.08 ; 5366,3343.68 8597.49,3343.68 ; 5703.86,2597.76 5703.86,3468 ; 6035.86,2597.76 6035.86,3468 ; 6672.43,2597.76 6672.43,3468 ; 6931.57,2597.76 6931.57,3468 ; 7306.72,2597.76 7306.72,3468 ; 8031.05,2597.76 8031.05,3468 ; 5366,2597.76 8597.49,2597.76 8597.49,3468 5366,3468 5366,2597.76
  text "Symbol" at 5440.59,3380.98 h72
  text "Quantity" at 5741.16,3380.98 h72
  text "Finished Hole Size" at 6073.16,3380.98 h72
  text "Plated" at 6709.72,3380.98 h72
  text "Hole Type" at 6968.86,3380.98 h72
  text "Drill Layer Pair" at 7344.02,3380.98 h72
  text "Hole Tolerance" at 8068.35,3380.98 h72
  text "11" at 5741.16,3256.66 h60
  text "8.00mil (0.203mm)" at 6073.16,3256.66 h60
  text "PTH" at 6709.72,3256.66 h60
  text "Round" at 6968.86,3256.66 h60
  text "Top Layer - Bottom Layer" at 7344.02,3256.66 h60
  text "42" at 5741.16,3132.34 h60
  text "16.00mil (0.406mm)" at 6073.16,3132.34 h60
  text "PTH" at 6709.72,3132.34 h60
  text "Round" at 6968.86,3132.34 h60
  text "Top Layer - Bottom Layer" at 7344.02,3132.34 h60
  text "16" at 5741.16,3008.02 h60
  text "40.00mil (1.016mm)" at 6073.16,3008.02 h60
  text "PTH" at 6709.72,3008.02 h60
  text "Round" at 6968.86,3008.02 h60
  text "Top Layer - Bottom Layer" at 7344.02,3008.02 h60
  text "15" at 5741.16,2883.7 h60
  text "43.31mil (1.100mm)" at 6073.16,2883.7 h60
  text "PTH" at 6709.72,2883.7 h60
  text "Round" at 6968.86,2883.7 h60
  text "Top Layer - Bottom Layer" at 7344.02,2883.7 h60
  text "+/-1.97mil" at 8068.35,2883.7 h60
  text "4" at 5741.16,2759.38 h60
  text "125.98mil (3.200mm)" at 6073.16,2759.38 h60
  text "PTH" at 6709.72,2759.38 h60
  text "Round" at 6968.86,2759.38 h60
  text "Top Layer - Bottom Layer" at 7344.02,2759.38 h60
  text "88 Total" at 5741.16,2635.06 h60
  text ".Layer_Name" at 577,-858.49 h60
M17 Embedded Cavity:
  text ".Layer_Name" at 577,-858.49 h60
M18 Embedded Assembly:
  text ".Layer_Name" at 577,-858.49 h60
M19 Embedded Keepout:
  text ".Layer_Name" at 567,-858.49 h60

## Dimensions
0,-400 to 1000,-400 on M2 Board Dimensions
0,0 to 4950,0 on M2 Board Dimensions
0,0 to 0,3450 on M2 Board Dimensions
